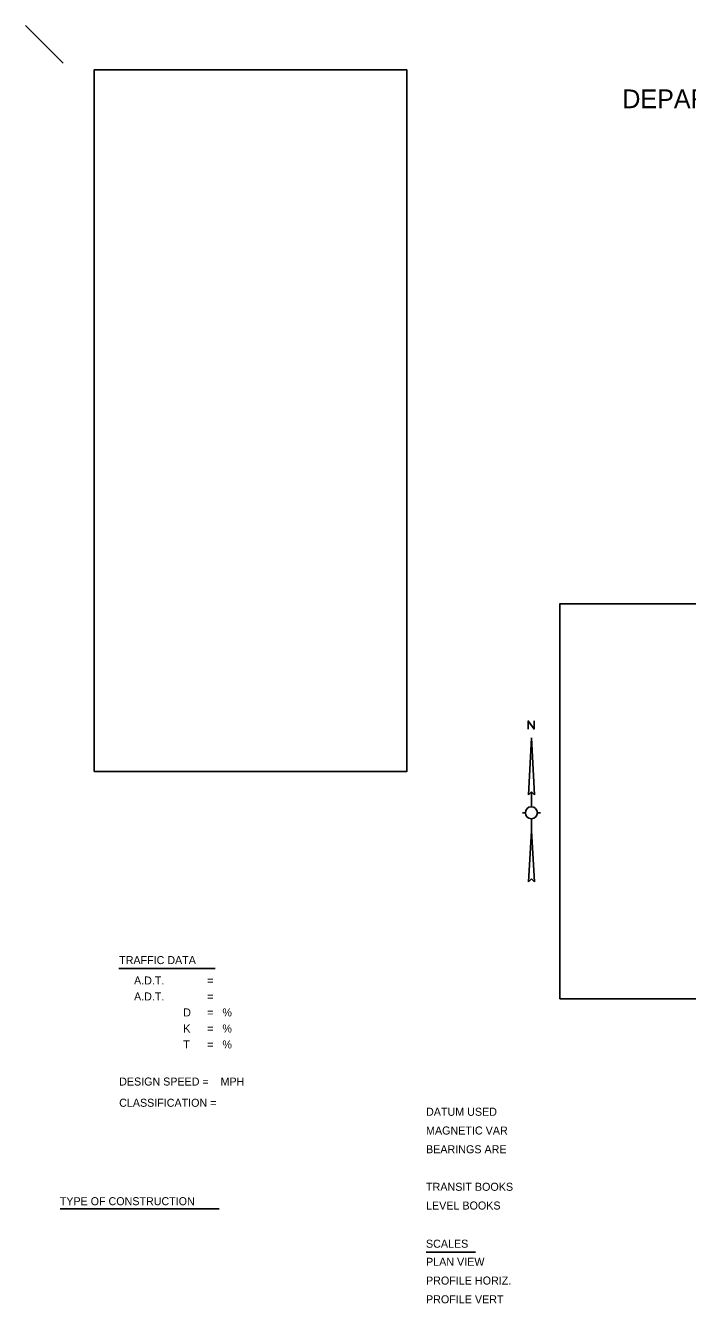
# Model space of a CAD drawing. Extents: x 0.19 to 2.82, y 0.04 to 1.79.
# Drawn here: x 0.192 to 1.074, y 0.088 to 1.792 of the extents above; entities that cross this region are included whole.
import ezdxf

# ---------------------------------------------------------------- set-up
doc = ezdxf.new("R2010")
doc.units = 0
for name, color, linetype in [('Annotation', 7, 'Continuous'), ('Layout Map Info', 7, 'Continuous'), ('Standard Info', 7, 'Continuous')]:
    doc.layers.add(name, color=color, linetype=linetype)

msp = doc.modelspace()

# ---------------------------------------------------------------- linework, layer by layer
at = {"layer": 'Annotation'}
msp.add_line((0.7256, 0.1568), (0.7915, 0.1568), dxfattribs=at)
msp.add_lwpolyline([(0.2833, 0.7972), (0.7, 0.7972), (0.7, 1.7327), (0.2833, 1.7327)], close=True, dxfattribs=at)
at = {"layer": 'Layout Map Info'}
msp.add_lwpolyline([(0.9038, 0.4943), (2.1045, 0.4943), (2.1045, 1.0206), (0.9038, 1.0206)], close=True, dxfattribs=at)
at = {"layer": 'Standard Info'}
for p, q in [((0.1917, 1.7917), (0.2417, 1.7417)), ((0.866, 0.8423), (0.862, 0.7663)), ((0.87, 0.7663), (0.866, 0.8423)), ((0.862, 0.7663), (0.866, 0.7703)), ((0.866, 0.7503), (0.866, 0.7703)), ((0.866, 0.7703), (0.87, 0.7663)), ((0.854, 0.7423), (0.858, 0.7423)), ((0.866, 0.7183), (0.866, 0.7343)), ((0.874, 0.7423), (0.878, 0.7423)), ((0.866, 0.7183), (0.862, 0.6503)), ((0.87, 0.6503), (0.866, 0.7183)), ((0.862, 0.6503), (0.866, 0.6543)), ((0.866, 0.6543), (0.87, 0.6503)), ((0.3161, 0.5345), (0.4445, 0.5345)), ((0.2376, 0.2142), (0.4497, 0.2142))]:
    msp.add_line(p, q, dxfattribs=at)
msp.add_lwpolyline([(0.8619, 0.8538), (0.8619, 0.8648), (0.8697, 0.8538), (0.8697, 0.8648)], dxfattribs=at)
msp.add_circle((0.866, 0.7423), 0.008, dxfattribs=at)

# ---------------------------------------------------------------- texts
for s, height, p in [('DEPARTMENT  OF  TRANSPORTATION  AND  DEVELOPMENT', 0.025, (0.9873, 1.6815)), ('TRAFFIC DATA', 0.01067, (0.3165, 0.5406)), ('     A.D.T.', 0.010667, (0.3165, 0.5134)), ('=        ', 0.01067, (0.4339, 0.5134)), ('     A.D.T.', 0.010667, (0.3165, 0.4921)), ('=        ', 0.01067, (0.4339, 0.4921)), ('D', 0.0107, (0.4019, 0.4708)), ('=   %', 0.01067, (0.4339, 0.4708)), ('K', 0.0107, (0.4019, 0.4494)), ('=   %', 0.01067, (0.4339, 0.4494)), ('T', 0.0107, (0.4019, 0.4281)), ('=   %', 0.01067, (0.4339, 0.4281)), ('DESIGN SPEED =    MPH', 0.010667, (0.3165, 0.3787)), ('CLASSIFICATION =     ', 0.010667, (0.3165, 0.3504)), ('DATUM USED                    ', 0.0107, (0.7256, 0.3384)), ('MAGNETIC VAR                  ', 0.0107, (0.7256, 0.3134)), ('BEARINGS ARE                  ', 0.0107, (0.7256, 0.2884)), ('TRANSIT BOOKS                 ', 0.0107, (0.7256, 0.2384)), ('TYPE OF CONSTRUCTION', 0.01067, (0.2373, 0.2192)), ('LEVEL BOOKS                   ', 0.0107, (0.7256, 0.2134)), ('SCALES', 0.0107, (0.7255, 0.1625)), ('PLAN VIEW                      ', 0.0107, (0.7256, 0.1384)), ('PROFILE HORIZ.                 ', 0.0107, (0.7256, 0.1134)), ('PROFILE VERT                  ', 0.0107, (0.7256, 0.0884))]:
    msp.add_text(s, height=height, dxfattribs=at).set_placement(p)

doc.saveas('drawing.dxf')
